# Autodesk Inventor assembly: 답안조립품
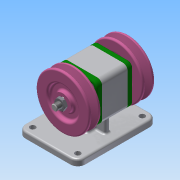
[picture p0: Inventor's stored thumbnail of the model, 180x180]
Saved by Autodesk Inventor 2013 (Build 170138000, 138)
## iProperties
Created: 2020-11
Part Number: 답안조립품
Document SubType Name: Assembly
Designer: Administrator
Author: Administrator
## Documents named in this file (10)
- C:\Users\Administrator\Desktop\701106v1047\답안조립품.iam
- C:\Users\Administrator\Desktop\701106v1047\본체.ipt
- C:\Users\Administrator\Desktop\701106v1047\베어링 6004.ipt
- C:\Users\Administrator\Desktop\701106v1047\오일 실 17 30 5.ipt
- C:\Users\Administrator\Desktop\701106v1047\커버.ipt
- C:\Users\Administrator\Desktop\701106v1047\축.ipt
- C:\Users\Administrator\Desktop\701106v1047\키 5 x 5 x 12.ipt
- C:\Users\Administrator\Desktop\701106v1047\V-벨트풀리.ipt
- C:\Users\Administrator\Desktop\701106v1047\너트 M10x1.ipt
- C:\Users\Administrator\Desktop\701106v1047\볼트 M4.ipt
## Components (2 placed, 1 different names)
1. V-벨트풀리:1 — 각도:3
2. V-벨트풀리:2 — 각도:4
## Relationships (2: Angle 2)
- 각도:3 [Angle]: V-벨트풀리:1
- 각도:4 [Angle]: V-벨트풀리:2
